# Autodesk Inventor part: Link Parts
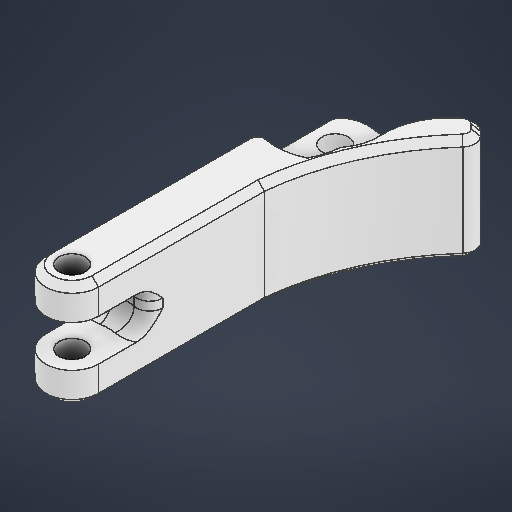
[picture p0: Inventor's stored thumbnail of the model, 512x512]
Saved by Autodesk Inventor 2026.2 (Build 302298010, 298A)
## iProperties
Created: 2026-05
Part Number: Link Parts
Material: ABS 플라스틱
Document SubType Name: Modeling
Designer: work
Density: 1.06 g/cm^3
Appearance: 매끄러움 - 흰색
Author: work
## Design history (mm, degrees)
sketch "스케치1"
  geometry: L1 (0, 0)-(0, -40); L2 (0, 0)-(0, -40); L3 (-4, 0)-(-4, -40); L4 (4, -40)-(4, 0); C1 r 2 at (0, 0); C2 r 2 at (0, -40); A1 r 4 centre (0, 0) between (4, 0) and (-4, 0); A2 r 4 centre (0, -40) between (-4, -40) and (4, -40); 2 further points
  constraints: 10 end point, 4 centre point, 4 point on circle, 4 tangent, 2 coincident, 2 vertical, 1 midpoint, 1 parallel
  dimensions: "d0" = 4 diameter of C1; "d1" = 40 distance of L1.start L1.end; "d2" = 4 diameter of C2; "d3" = 4 radius of A1
extrude "돌출1" new body sketch "스케치1" stored distance "d4" = 16; taper "d5" = 0 deg
sketch "스케치2"
  geometry: C1 r 8 at (0, 0); 1 further point
  constraints: 1 centre point, 1 coincident
  dimensions: "d6" = 16 diameter of C1
extrude "돌출2" cut sketch "스케치2" stored distance "d7" = 6.3; taper "d8" = 0 deg
sketch "스케치3"
  geometry: L1 (-4, 40)-(-4, 0) reference; L2 (4, 0)-(4, 40) reference; C1 r 2 at (0, 40) reference; C2 r 2 at (0, 0) reference; C3 r 8 at (0, 40); A1 r 4 centre (0, 40) between (4, 40) and (-4, 40) reference; A2 r 4 centre (0, 0) between (-4, 0) and (4, 0) reference; 1 further point
  constraints: 1 centre point, 1 coincident
  dimensions: "d9" = 16 diameter of C3
extrude "돌출3" cut sketch "스케치3" distance "d10" = 4.2; taper "d11" = 0 deg
node "작업 평면1"
sketch "스케치4"
  geometry: L1 (0, 40)-(9.192, 49.192); L2 (4, 33.072)-(4, 0) reference; L3 (4, 33.072)-(4, 40) reference; L4 (8.227, 48.227)-(11.055, 51.055); L5 (11.055, 51.055)-(14.566, 47.545); L6 (11.071, 39.757)-(4, 32.686); L7 (4, 0)-(4, 33.072) reference; C1 r 5.5 at (0, 40); A1 r 11 centre (16.473, 40.946) between (9.192, 49.192) and (8.227, 48.227); A2 r 4 centre (0, 40) between (4, 40) and (-4, 40) reference; A3 r 6 centre (18.808, 43.303) between (14.566, 47.545) and (12.818, 43.651); A4 r 6 centre (6.828, 44) between (11.071, 39.757) and (12.818, 43.651); A5 r 18 centre (22, 25.23) between (9.272, 37.958) and (4, 25.23); 7 further points
  constraints: 8 end point, 8 point on circle, 5 centre point, 5 point on line, 5 tangent, 1 concentric, 1 line through centre, 1 parallel, 1 perpendicular
  dimensions: "d17" = 11 diameter of C1; "d18" = 22 diameter of A1; "d19" = 13 distance of L1.start L1.end; "d20" = 135 deg angle of L3 L1; "d21" = 4 distance of L4.start L4.end; "d22" = 8 distance between parallel lines of L1 L6; "d23" = 6 radius of A3; "d24" = 6 radius of A4; "d26" = 10 distance of L6.end L6.start; "d27" = 18 radius of A5
extrude "돌출4" join sketch "스케치4" stored distance "d28" = 10; taper "d29" = 0 deg
sketch "스케치5"
  geometry: L1 (-4, 0)-(-4, 6.928) reference; L2 (4, 3.775)-(4, 0) reference; L3 (4, 6.928)-(4, 3.775) reference; L4 (-4, 0)-(-4, -3.775); C1 r 2 at (0, 0) reference; A1 r 4 centre (0, 0) between (-4, 0) and (4, 0) reference; A2 r 8 centre (0, 0) between (4, 6.928) and (-4, 6.928) reference; A3 r 11 centre (16.473, -0.946) between (5.491, -0.315) and (8.227, -8.227) reference; A4 r 5.5 centre (0, 0) between (5.491, -0.315) and (0.948, -5.418); A5 r 11 centre (16.473, -0.946) between (9.192, -9.192) and (11.402, -10.708) reference; A6 r 8 centre (2.326, -13.298) between (9.192, -9.192) and (0.948, -5.418); 3 further points
  constraints: 5 point on circle, 2 centre point, 2 end point, 1 coincident, 1 tangent, 1 vertical
  dimensions: "d30" = 8 radius of A6
extrude "돌출5" join sketch "스케치5" stored distance "d31" = 10; taper "d32" = 0 deg
sketch "스케치6"
  geometry: L1 (14.566, 47.545)-(11.402, 50.708) reference; L2 (-4, 33.072)-(-4, 0) reference; L3 (4, 0)-(4, 25.23) reference; L4 (9.272, 37.958)-(11.071, 39.757) reference; L5 (14.566, 47.545)-(11.402, 50.708) reference; L6 (9.192, 49.192)-(8.227, 48.227) reference; L7 (4, 36.225)-(4, 33.072) reference; L8 (4, 36.225)-(4, 33.072) reference; C1 r 2 at (0, 0) reference; A1 r 18 centre (22, 25.23) between (9.272, 37.958) and (4, 25.23) reference; A2 r 36.686 centre (40.507, 21.604) between (14.566, 47.545) and (4, 25.23); A3 r 8 centre (0, 40) between (-4, 33.072) and (4, 33.072) reference; A4 r 4 centre (0, 0) between (-4, 0) and (4, 0) reference; A5 r 18 centre (22, 25.23) between (9.272, 37.958) and (4, 25.23) reference; A6 r 6 centre (6.828, 44) between (11.071, 39.757) and (12.818, 43.651) reference; A7 r 6 centre (18.808, 43.303) between (14.566, 47.545) and (12.818, 43.651) reference; A8 r 11 centre (16.473, 40.946) between (11.402, 50.708) and (9.192, 49.192) reference; A9 r 11 centre (16.473, 40.946) between (8.227, 48.227) and (5.491, 40.315) reference; A10 r 5.5 centre (0, 40) between (4, 36.225) and (5.491, 40.315) reference; A11 r 8 centre (-4, 36.225) between (3.156, 32.649) and (4, 36.225); 4 further points
  constraints: 6 point on circle, 2 centre point, 1 line through centre, 1 tangent
  dimensions: "d33" = 8 radius of A11
  node "투영된 루프3"
extrude "돌출6" join sketch "스케치6" stored distance "d34" = 10; taper "d35" = 0 deg
extrude "돌출7" cut sketch "스케치6" extent not by distance; stored distance "d36" = 10; taper "d37" = 0 deg
fillet "모깎기3" dims "d38" = 2
fillet "모깎기4" dims "d39" = 2.5
chamfer "모따기2" distance "d40" = 1; stored, may be unused: second distance "d41" = 2, angle "d42" = 45 deg
sketch "스케치7"
  geometry: L1 (-4, 34.233)-(-4, 42.872) reference; L2 (8.957, 47.542)-(9.877, 48.463) reference; L3 (-3, 0)-(-3, 30.202) reference; L4 (3, 25.28)-(3, 0) reference; L5 (11.816, 48.88)-(12.481, 48.216) reference; C1 r 2 at (0, 40) reference; C2 r 2 at (0, 0) reference; C3 r 5.8 at (0, 40); A1 r 4.5 centre (-2, 30.202) between (-1.1, 34.611) and (-4, 34.233) reference; A2 r 5.5 centre (0, 40) between (-1.1, 34.611) and (4.379, 36.672) reference; A3 r 5.5 centre (0, 40) between (4.379, 36.672) and (5.491, 40.315) reference; A4 r 11 centre (16.473, 40.946) between (7.32, 47.048) and (5.491, 40.315) reference; A5 r 8 centre (2.326, 53.298) between (0.948, 45.418) and (7.32, 47.048) reference; A6 r 5.5 centre (0, 40) between (0.948, 45.418) and (-3.143, 44.514) reference; A7 r 2 centre (-2, 42.872) between (-3.143, 44.514) and (-4, 42.872) reference; A8 r 10 centre (16.473, 40.946) between (8.957, 47.542) and (6.489, 40.373) reference; A9 r 6.5 centre (0, 40) between (5.175, 36.066) and (6.489, 40.373) reference; A10 r 1 centre (5.971, 35.461) between (5.175, 36.066) and (4.974, 35.538) reference; A11 r 9 centre (-4, 36.225) between (3.882, 31.88) and (4.974, 35.538) reference; A12 r 9 centre (0, 40) between (-1.8, 31.182) and (3.882, 31.88) reference; A13 r 1 centre (-2, 30.202) between (-1.8, 31.182) and (-3, 30.202) reference; A14 r 3 centre (0, 0) between (-3, 0) and (3, 0) reference; A15 r 37.686 centre (40.507, 21.604) between (12.516, 46.839) and (3, 25.28) reference; A16 r 1 centre (11.774, 47.509) between (12.516, 46.839) and (12.481, 48.216) reference; A17 r 1 centre (11.109, 48.173) between (11.816, 48.88) and (10.513, 48.976) reference; A18 r 10 centre (16.473, 40.946) between (10.513, 48.976) and (9.877, 48.463) reference; 3 further points
  constraints: 1 centre point, 1 coincident
  dimensions: "d43" = 0.3 radial gap between concentric circles of A3 C3
extrude "돌출8" cut sketch "스케치7" stored distance "d44" = 10; taper "d45" = 0 deg
chamfer "모따기3" distance "d46" = 0.5; stored, may be unused: second distance "d47" = 2, angle "d48" = 45 deg
node "솔리드1"
mirror "미러1"
mirror "미러2"
node "투영된 루프1"
node "투영된 루프2"
node "투영된 루프4"
node "투영된 루프5"
